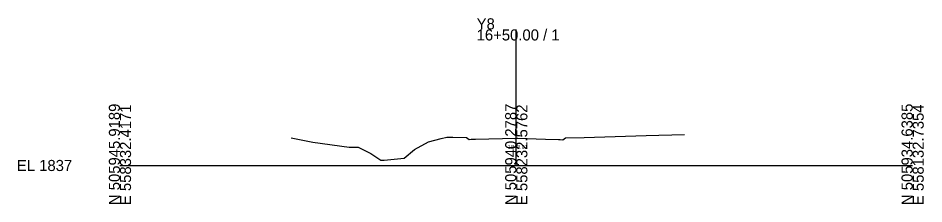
# Model space of a CAD drawing. Extents: x -26 to 203, y -10 to 8070.
# Drawn here: x -25.7 to 202.8, y 6490.3 to 6537.2 of the extents above; entities that cross this region are included whole.
import ezdxf

# ---------------------------------------------------------------- set-up
doc = ezdxf.new("R2010")
doc.units = 0
for name, color, linetype in [('Default', 7, 'Continuous'), ('Exist Cross Section Cell', 7, 'Continuous'), ('Exist XS Center Line Elevation Label', 7, 'Continuous'), ('Exist XS Ground Line', 7, 'Continuous')]:
    doc.layers.add(name, color=color, linetype=linetype)

msp = doc.modelspace()

# ---------------------------------------------------------------- linework, layer by layer
at = {"layer": 'Exist Cross Section Cell'}
for p, q in [((100, 6500), (100, 6534.35)), ((0, 6500), (100, 6500)), ((100, 6500), (200, 6500))]:
    msp.add_line(p, q, dxfattribs=at)
at = {"layer": 'Exist XS Ground Line'}
for p, q in [((43.17, 6506.97), (48.69, 6505.9)), ((77.89, 6505.99), (81.06, 6506.77)), ((81.06, 6506.77), (82.44, 6507.15)), ((82.44, 6507.15), (83.98, 6507.12)), ((83.98, 6507.12), (87.48, 6507.06)), ((87.48, 6507.06), (88.11, 6506.6)), ((88.11, 6506.6), (88.59, 6506.61)), ((88.59, 6506.61), (89.7, 6506.64)), ((89.7, 6506.64), (93.07, 6506.74)), ((93.07, 6506.74), (100, 6506.91)), ((100, 6506.91), (100.42, 6506.92)), ((100.42, 6506.92), (107.36, 6506.63)), ((107.36, 6506.63), (110.67, 6506.52)), ((110.67, 6506.52), (111.05, 6506.52)), ((111.05, 6506.52), (111.78, 6506.5)), ((111.78, 6506.5), (112.38, 6507.02)), ((112.38, 6507.02), (117.11, 6507.04)), ((117.11, 6507.04), (132.79, 6507.6)), ((132.79, 6507.6), (142.46, 6507.85)), ((48.69, 6505.9), (57.8, 6504.61)), ((57.8, 6504.61), (60.11, 6504.62)), ((60.11, 6504.62), (63.3, 6503.03)), ((71.7, 6501.83), (74.32, 6504.07)), ((74.32, 6504.07), (77.89, 6505.99)), ((63.3, 6503.03), (65.79, 6501.34)), ((66.7, 6501.31), (71.7, 6501.83)), ((65.79, 6501.34), (66.7, 6501.31))]:
    msp.add_line(p, q, dxfattribs=at)

# ---------------------------------------------------------------- texts
at = {"layer": 'Default'}
msp.add_text('-', height=0.0001, dxfattribs=at).set_placement((0, 6500))
at = {"layer": 'Exist Cross Section Cell'}
for s, p in [('Y8', (90, 6534.35)), ('16+50.00 / 1', (90, 6531.55)), ('EL 1837', (-26, 6498.6))]:
    msp.add_text(s, height=2.8, dxfattribs=at).set_placement(p)
for s, p in [('N 505945.9189', (0, 6490)), ('E 558332.4171', (2.8, 6490)), ('N 505940.2787', (100, 6490)), ('E 558232.5762', (102.8, 6490)), ('N 505934.6385', (200, 6490)), ('E 558132.7354', (202.8, 6490))]:
    msp.add_text(s, height=2.8, rotation=90, dxfattribs=at).set_placement(p)
at = {"layer": 'Exist XS Center Line Elevation Label'}
msp.add_text('1843.91', height=1, dxfattribs=at).set_placement((97.89, 6504.16))

doc.saveas('drawing.dxf')
